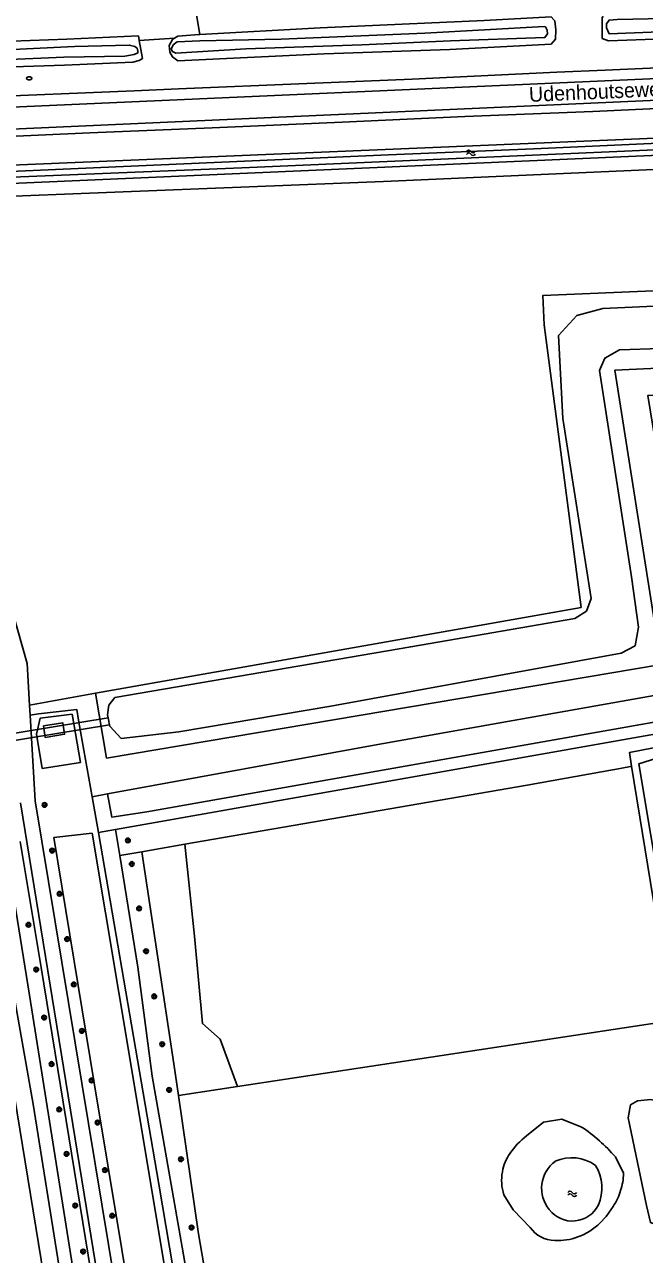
# Model space of a CAD drawing. Extents: x 133000 to 136000, y 400500 to 403500.
# Drawn here: x 134103.1 to 134208.5, y 402290.6 to 402499.8 of the extents above; entities that cross this region are included whole.
import ezdxf

# ---------------------------------------------------------------- set-up
doc = ezdxf.new("R2010")
doc.units = 0
for name, color, linetype in [('gg-anno-openbare ruimte label', 7, 'Continuous'), ('gg-knt-BGT kruinlijn', 7, 'Continuous'), ('gg-knt-bovenkant onderkant talud', 7, 'Continuous'), ('gg-knt-onverhard', 7, 'Continuous'), ('gg-knt-verharding', 7, 'Continuous'), ('gg-knt-verharding nz', 7, 'Continuous'), ('gg-kntw-bovenkant insteek waterloop', 7, 'Continuous'), ('gg-kntw-waterlijn', 7, 'Continuous'), ('gg-kwrk-duiker element', 7, 'Continuous'), ('gg-kwrk-duiker nz vlak', 7, 'Continuous'), ('gt-grn-groengrens', 7, 'Continuous'), ('gt-symb-boom', 7, 'Continuous'), ('gt-symb-brandkraan', 7, 'Continuous'), ('gt-symb-watersymbool', 7, 'Continuous'), ('gx-grn-maaiveld', 7, 'Continuous')]:
    doc.layers.add(name, color=color, linetype=linetype)

# ---------------------------------------------------------------- blocks, each defined once
blk = doc.blocks.new('gt0-WA')
at = {"layer": 'gt-symb-watersymbool'}
for centre, start, end in [((-0.32, 0.02), 28.0725, 151.9275), ((0.43, 0.42), 208.0725, 331.9275), ((-0.32, -0.43), 28.0725, 151.9275), ((0.43, -0.03), 208.0725, 331.9275)]:
    blk.add_arc(centre, 0.425, start, end, dxfattribs=at)
blk = doc.blocks.new('gt0-BOOM')
at = {"layer": 'gt-symb-boom'}
for radius in [0.4, 0.2]:
    blk.add_circle((0, 0), radius, dxfattribs=at)
blk = doc.blocks.new('gt0-BR')
at = {"layer": 'gt-symb-brandkraan'}
for centre, radius, start, end in [((-0.24, 0), 0.206, 107.5669, 252.4331), ((0.6, -2.66), 3, 106.892, 107.5669), ((0, -0.69), 0.938, 73.108, 106.892), ((-0.6, -2.66), 3, 72.4331, 73.108), ((0.24, 0), 0.206, 287.567, 72.4331), ((0.6, 2.66), 3, 252.4331, 253.108), ((0, 0.69), 0.938, 253.108, 286.8921), ((-0.6, 2.66), 3, 286.8921, 287.567)]:
    blk.add_arc(centre, radius, start, end, dxfattribs=at)

msp = doc.modelspace()

# ---------------------------------------------------------------- linework, layer by layer
at = {"layer": 'gg-knt-BGT kruinlijn'}
msp.add_lwpolyline([(134313.12, 402344.51), (134219.57, 402328.02), (134211.52, 402375.28), (134207.56, 402374.04), (134215.51, 402326.66), (134231.32, 402235.26)], dxfattribs=at)
at = {"layer": 'gg-knt-bovenkant onderkant talud'}
msp.add_line((134213.36, 402330.39), (134206.34, 402373.65), dxfattribs=at)
msp.add_lwpolyline([(134206.34, 402373.65), (134205.96, 402375.96), (134212.08, 402377.18), (134212.53, 402374.84)], dxfattribs=at)
at = {"layer": 'gg-knt-onverhard'}
msp.add_line((134104.06, 402382.32), (134103.96, 402384.05), dxfattribs=at)
for points in [[(134103.96, 402384.05), (134103.56, 402391.1), (134098.72, 402407.93), (134096.8, 402436.31)], [(134129.87, 402216.81), (134104.89, 402367.78), (134104.06, 402382.32)], [(134159.26, 402018.98), (134156.12, 402037.37), (134102.42, 402367.39)]]:
    msp.add_lwpolyline(points, dxfattribs=at)
at = {"layer": 'gg-knt-verharding'}
for p, q in [((134201.86, 402492.06), (134193.61, 402491.67)), ((134201.86, 402492.06), (134226.14, 402493.15)), ((134121.71, 402488.52), (134129.29, 402488.85))]:
    msp.add_line(p, q, dxfattribs=at)
for points in [[(134129.29, 402488.85), (134151.11, 402489.74), (134169.04, 402490.52), (134193.61, 402491.67)], [(134121.71, 402488.52), (134094.05, 402487.4), (134089.46, 402487.21)], [(134226.41, 402486.23), (134199.77, 402485.01), (134178, 402484.13), (134157.14, 402483.21), (134135.02, 402482.24), (134114.18, 402481.39), (134095.33, 402480.55)]]:
    msp.add_lwpolyline(points, dxfattribs=at)
at = {"layer": 'gg-knt-verharding nz'}
for p, q in [((134075.36, 402484.59), (134226.21, 402491.3)), ((134075.53, 402480.87), (134226.35, 402487.65))]:
    msp.add_line(p, q, dxfattribs=at)
at = {"layer": 'gg-kntw-bovenkant insteek waterloop'}
for p, q in [((134112.58, 402374.29), (134111.21, 402382.47)), ((134106.11, 402373.24), (134112.58, 402374.29)), ((134114.6, 402362.26), (134108.05, 402361.5)), ((134121.42, 402321.6), (134114.6, 402362.26)), ((134108.05, 402361.5), (134114.93, 402319.8)), ((134203.59, 402307.18), (134204.96, 402304.41))]:
    msp.add_line(p, q, dxfattribs=at)
for points in [[(134288.78, 402480.98), (134288.74, 402483.77), (134095.45, 402475.64), (134095.6, 402472.55), (134288.78, 402480.98)], [(134293.18, 402458), (134191.27, 402453.71), (134191.48, 402448.71)], [(134191.48, 402448.71), (134197.76, 402400.64), (134115.18, 402386.08)], [(134115.18, 402386.08), (134117.04, 402375.02), (134211.39, 402390.93), (134203.51, 402440.99), (134294.04, 402445.19)], [(134111.21, 402382.47), (134105.73, 402381.81), (134105.14, 402379.1), (134106.11, 402373.24)], [(134133.56, 402219.68), (134132.58, 402219.75), (134131.33, 402221.09), (134114.93, 402319.8)], [(134121.42, 402321.6), (134138.34, 402219.76), (134136.17, 402219.61)], [(134188.48, 402310.76), (134191.38, 402313.12), (134194.49, 402313.59), (134197.73, 402312.33)], [(134189.07, 402295.2), (134186.17, 402298.21), (134184.61, 402300.76)], [(134203.2, 402298.77), (134202, 402297.07), (134200.99, 402295.97)]]:
    msp.add_lwpolyline(points, dxfattribs=at)
for centre, radius, start, end in [((134182.08, 402288.58), 28.44, 48.6729, 56.629), ((134196.29, 402300.5), 12.89, 127.3004, 145.4843), ((134182.04, 402288.57), 28.47, 40.8121, 48.6238), ((134192.36, 402303.2), 8.13, 145.4473, 169.6645), ((134192.37, 402303.19), 8.14, 169.6161, 197.3993), ((134194.39, 402304.6), 10.57, 342.6536, 358.9681), ((134194.45, 402304.59), 10.51, 326.3805, 342.6131), ((134193.46, 402298.37), 5.42, 215.822, 268.1741), ((134193.62, 402303.46), 10.51, 289.8853, 314.5422), ((134193.62, 402303.46), 10.51, 268.1611, 289.8535)]:
    msp.add_arc(centre, radius, start, end, dxfattribs=at)
at = {"layer": 'gg-kntw-waterlijn'}
msp.add_line((134117.32, 402381.88), (134117.54, 402380.7), dxfattribs=at)
for points in [[(134096.77, 402474.64), (134096.77, 402473.65), (134140.04, 402475.45), (134246.76, 402480.08), (134267.45, 402480.97), (134288.14, 402481.87), (134288.09, 402482.94), (134276.45, 402482.44), (134212.19, 402479.65), (134189.73, 402478.68), (134164.99, 402477.61), (134126.34, 402475.93), (134096.77, 402474.64)], [(134292.52, 402452.89), (134290.34, 402455.58), (134245, 402453.5), (134201.44, 402451.51), (134197.02, 402450.28), (134193.91, 402446.88), (134194.65, 402432.76), (134199.44, 402402.15), (134198.69, 402400.02), (134196.67, 402398.75), (134168.79, 402393.97), (134118.45, 402385.33), (134117.4, 402384.05), (134117.22, 402382.4), (134117.32, 402381.88)], [(134117.54, 402380.7), (134117.59, 402380.43), (134119.53, 402378.35), (134129.33, 402379.5), (134155.19, 402383.88), (134204.56, 402392.87), (134206.93, 402394.14), (134207.5, 402397.31), (134206.35, 402405.84), (134200.88, 402440.94), (134201.8, 402443.07), (134204.27, 402444.46), (134246.1, 402445.84), (134291.03, 402448.09), (134292.24, 402449.07), (134292.44, 402450.83), (134292.46, 402451.32)]]:
    msp.add_lwpolyline(points, dxfattribs=at)
for centre, radius, start, end in [((134196.7, 402301.86), 5.67, 126.2175, 219.7954), ((134196.18, 402300.29), 6.77, 53.3275, 114.7083), ((134193.78, 402301.9), 7.49, 337.3554, 30.6224), ((134196.27, 402301.22), 4.94, 217.2937, 333.5494)]:
    msp.add_arc(centre, radius, start, end, dxfattribs=at)
at = {"layer": 'gg-kwrk-duiker element'}
msp.add_lwpolyline([(134106.34, 402380.51), (134106.59, 402378.55), (134109.91, 402379.07), (134109.61, 402381), (134106.34, 402380.51)], dxfattribs=at)
at = {"layer": 'gg-kwrk-duiker nz vlak'}
for p, q in [((134117.32, 402381.88), (134098.65, 402378.79)), ((134117.54, 402380.7), (134098.86, 402377.6))]:
    msp.add_line(p, q, dxfattribs=at)
at = {"layer": 'gt-grn-groengrens'}
for p, q in [((134115.18, 402386.08), (134103.96, 402384.05)), ((134112.29, 402381.49), (134112.63, 402379.55)), ((134112.63, 402379.55), (134114.61, 402368.46)), ((134206.14, 402373.61), (134206.34, 402373.65)), ((134117.21, 402368.94), (134114.61, 402368.46)), ((134114.61, 402368.46), (134115.68, 402362.39)), ((134115.68, 402362.39), (134118.57, 402362.9)), ((134119.29, 402358.45), (134118.57, 402362.9)), ((134130.33, 402360.36), (134123.04, 402359.1)), ((134123.04, 402359.1), (134119.29, 402358.45)), ((134213.36, 402330.39), (134139.31, 402319.15))]:
    msp.add_line(p, q, dxfattribs=at)
for points in [[(134289.24, 402478.68), (134164.15, 402473.12), (134095.52, 402470.38)], [(134296.32, 402440.88), (134218.3, 402437.14), (134209.11, 402436.7), (134211.27, 402423.46), (134217.11, 402390.39), (134217.21, 402386.9), (134163.18, 402377.36), (134117.21, 402368.94)], [(134117.21, 402368.94), (134117.94, 402364.97), (134123.91, 402365.89), (134222.98, 402383.4), (134214.12, 402432.39), (134297.09, 402436.09)], [(134118.57, 402362.9), (134124.34, 402363.92), (134225.3, 402381.78), (134216.49, 402430.49), (134297.41, 402434.1)], [(134104.06, 402382.32), (134105.48, 402382.54), (134111.97, 402383.29), (134112.29, 402381.49)], [(134203.45, 402373.1), (134188.58, 402370.44), (134130.33, 402360.36)], [(134206.14, 402373.61), (134203.49, 402373.1), (134203.45, 402373.1)], [(134115.68, 402362.39), (134125.95, 402302.56), (134135.57, 402245.61), (134140.08, 402218.38)], [(134155.86, 402017.23), (134144.85, 402086.63), (134122.24, 402222.65), (134114.7, 402266.81), (134103.95, 402334.7), (134101.6, 402349.18), (134099.88, 402360.41)], [(134158.36, 402018.51), (134156.83, 402027.78), (134132.3, 402178.02), (134105.89, 402339.38), (134102.35, 402360.84)], [(134139.31, 402319.15), (134136.38, 402327.24), (134133.34, 402329.86), (134131.99, 402344.72), (134130.33, 402360.36)], [(134142, 402218.57), (134139.6, 402233.72), (134130.27, 402289.59), (134124.78, 402320.91), (134122.36, 402339.48), (134119.29, 402358.45)], [(134129.28, 402317.62), (134128.49, 402323.01), (134123.04, 402359.1)], [(134097.59, 402355.35), (134104.56, 402316.17), (134109.13, 402287.34), (134112.1, 402267.18), (134121.25, 402212.86), (134127.31, 402177.98), (134132.12, 402149.89), (134138.18, 402115.12), (134141.89, 402090.51), (134150.67, 402037.76), (134154.13, 402017.23), (134155.86, 402017.23)], [(134112.3, 402250.46), (134095.84, 402351.15), (134026.88, 402339.06), (134037.68, 402278.66)], [(134129.28, 402317.62), (134132.69, 402294.11), (134142.03, 402239.82), (134145.7, 402218.94)]]:
    msp.add_lwpolyline(points, dxfattribs=at)
at = {"layer": 'gx-grn-maaiveld'}
for p, q in [((134128.58, 402497.47), (134122.61, 402497.06)), ((134139.31, 402319.15), (134129.28, 402317.62))]:
    msp.add_line(p, q, dxfattribs=at)
for points in [[(134167.48, 402754.51), (134182.27, 402724.42), (134188.87, 402710.28), (134205.69, 402688.71), (134205.92, 402685.48), (134207.02, 402676.12), (134206.13, 402668.19), (134200.45, 402658.52), (134144.39, 402635.58), (134107.44, 402620.48), (134110.46, 402594.97), (134111, 402594.89), (134112.4, 402594.28), (134115.05, 402591.35), (134115.99, 402589.34), (134117.37, 402578.55), (134120, 402563.66), (134125.1, 402535.83), (134128.07, 402522.53), (134130.57, 402511.93), (134132.93, 402498.08)], [(134201.55, 402501.15), (134201.36, 402501.03), (134201.31, 402499.22), (134201.36, 402497.43), (134202.42, 402497.01), (134230.46, 402498.07), (134269.04, 402499.44), (134300.63, 402500.93), (134302.17, 402501.14), (134303.23, 402501.98), (134303.54, 402503.09), (134303.49, 402504.42), (134302.59, 402505.32), (134302.57, 402505.33)], [(134202.05, 402499.92), (134202.05, 402499.25), (134202.52, 402498.23), (134228.24, 402499.23), (134261.42, 402500.66), (134293.86, 402501.93), (134300.95, 402502.46), (134302.17, 402502.67), (134302.77, 402503.6), (134302.54, 402504.31), (134301.69, 402504.47), (134283.43, 402503.68), (134261.37, 402502.67), (134227.71, 402501.19), (134203.9, 402500.66), (134202.52, 402500.55), (134202.05, 402499.92)], [(134193.11, 402500.61), (134193.31, 402500.41), (134193.45, 402498.91), (134193.39, 402497.31), (134192.64, 402496.48), (134175.41, 402495.57), (134154.06, 402494.81), (134129.14, 402493.62), (134128.23, 402494.3), (134127.79, 402495.09), (134127.71, 402496.24), (134128.27, 402497.27), (134128.58, 402497.47)], [(134132.93, 402498.08), (134153.35, 402499.26), (134181.25, 402500.49), (134192.64, 402501.08), (134193.11, 402500.61)], [(134092.72, 402495.29), (134092.78, 402495.61), (134094.29, 402496.4), (134100.92, 402496.96), (134110.29, 402497.31), (134122.47, 402497.87), (134122.61, 402497.06)], [(134128.38, 402496.32), (134128.04, 402495.62), (134128.24, 402495.22), (134128.84, 402494.92), (134140.71, 402495.68), (134160.43, 402496.37), (134175.54, 402497), (134191.61, 402497.6), (134192.01, 402498.23), (134191.99, 402498.85), (134191.68, 402499.38), (134191.45, 402499.45), (134171.17, 402498.33), (134146.71, 402497.3), (134132.91, 402497.04), (134129.06, 402496.88), (134128.38, 402496.32)], [(134132.93, 402498.08), (134132.08, 402498.03), (134129.14, 402497.83), (134128.58, 402497.47)], [(134092.72, 402495.29), (134092.55, 402494.35), (134093.14, 402493.15), (134094.21, 402492.39), (134109.89, 402492.91), (134121.52, 402493.42), (134122.59, 402493.66), (134123.15, 402494.02), (134122.61, 402497.06)], [(134093.21, 402494.67), (134093.2, 402494.39), (134093.32, 402493.98), (134094.09, 402493.63), (134099.27, 402493.82), (134109.77, 402494.22), (134120.17, 402494.43), (134121.76, 402494.69), (134122.34, 402494.96), (134122.36, 402495.26), (134122.24, 402495.75), (134121.84, 402496.04), (134120.91, 402496.31), (134111.6, 402496.04), (134096.39, 402495.35), (134095.14, 402495.3), (134093.77, 402495.12), (134093.21, 402494.67)], [(134207.37, 402316.72), (134209.59, 402316.93), (134211.34, 402316.51), (134214.04, 402296.98), (134213.4, 402295.4), (134211.71, 402295.24), (134209.54, 402296.03), (134208.85, 402298.94), (134205.78, 402313.86), (134206.15, 402316.03), (134207.37, 402316.72)]]:
    msp.add_lwpolyline(points, dxfattribs=at)

# ---------------------------------------------------------------- block references
at = {"layer": 'gt-symb-boom'}
for p in [(134106.5, 402367.05), (134107.77, 402359.28), (134120.67, 402361.03), (134121.32, 402357.01), (134109.04, 402351.96), (134122.58, 402349.46), (134103.75, 402346.68), (134110.32, 402344.23), (134123.75, 402342.18), (134105.08, 402339.06), (134111.46, 402336.53), (134125.15, 402334.5), (134106.41, 402330.89), (134112.85, 402328.62), (134126.5, 402326.36), (134107.69, 402322.99), (134114.49, 402320.21), (134127.67, 402318.59), (134108.99, 402315.26), (134115.5, 402313.02), (134110.24, 402307.7), (134116.76, 402304.95), (134129.7, 402306.78), (134111.71, 402298.91), (134118.01, 402297.17), (134131.49, 402295.17), (134113.05, 402291.08)]:
    msp.add_blockref('gt0-BOOM', p, dxfattribs=at)
at = {"layer": 'gt-symb-brandkraan'}
msp.add_blockref('gt0-BR', (134103.89, 402490.64), dxfattribs=at)
at = {"layer": 'gt-symb-watersymbool', "rotation": 2.0065389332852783}
msp.add_blockref('gt0-WA', (134178.94, 402477.97), dxfattribs=at)
at = {"layer": 'gt-symb-watersymbool'}
msp.add_blockref('gt0-WA', (134196.18, 402300.9), dxfattribs=at)

# ---------------------------------------------------------------- texts
at = {"layer": 'gg-anno-openbare ruimte label'}
msp.add_text('Udenhoutseweg', height=2.5, rotation=2.5, dxfattribs=at).set_placement((134188.94, 402486.63))

doc.saveas('drawing.dxf')
